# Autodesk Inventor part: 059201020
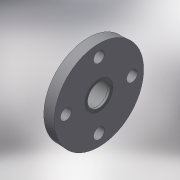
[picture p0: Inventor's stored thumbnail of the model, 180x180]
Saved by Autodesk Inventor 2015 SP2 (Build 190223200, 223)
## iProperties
Created: 2017-10
Part Number: 059201020
Material: Generic
Description: PLASSON THR. FIXED FLANGE PVC 2"
Document SubType Name: Modeling
Designer: KIM
Density: 1 g/cm^3
Appearance: Default
Author: KIM
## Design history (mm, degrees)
derived "059201.ipt"
feature "Solid1::059201.ipt"
tag "TaggingFeature1"
body "Solid1"
other parameters: "d0" = 39, "d2" = 165, "d3" = 163.35, "d14" = 18, "d15" = 62.5, "d16" = 39, "d17" = 0, "d19" = 360 deg, "d21" = 26, "d22" = 56.656, "d23" = 53.8232, "d25" = 0.56656, "d26" = 0.825, "d27" = 0.825, "d28" = 0.825, "d29" = 0.825, "d30" = 0.825, "d31" = 0.825, "d32" = 0.33, "d33" = 0, "d34" = 18, "d35" = 67.9872, "E_" = 165, "H_" = 39, "Dp_" = 125, "S_" = 18, "lt_" = 26, "G_" = 56.656, "H_1" = 18
